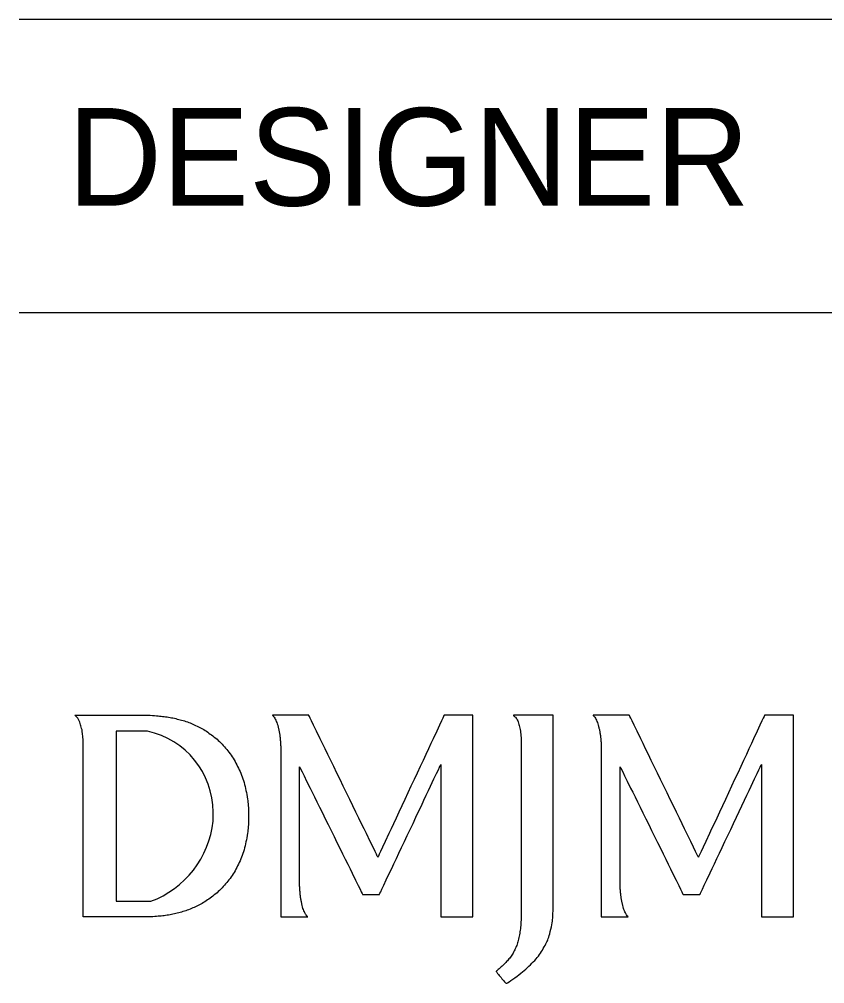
# Model space of a CAD drawing. Extents: x 0 to 3.5, y -0.08 to 2.5.
# Drawn here: x 3.1667 to 3.2526, y 1.7486 to 1.8514 of the extents above; entities that cross this region are included whole.
import ezdxf

# ---------------------------------------------------------------- set-up
doc = ezdxf.new("R2010")
doc.units = 0
doc.layers.add('G-ANNO-TTLB', color=7, linetype='Continuous')
doc.layers.add('G-DMJM-LOGO', color=7, linetype='Continuous')

msp = doc.modelspace()

# ---------------------------------------------------------------- linework, layer by layer
at = {"layer": 'G-ANNO-TTLB'}
msp.add_line((3.1666666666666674, 1.8201471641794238), (3.458333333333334, 1.8201471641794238), dxfattribs=at)
msp.add_lwpolyline([(3.1666666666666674, 1.8513971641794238), (3.458333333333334, 1.8513971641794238)], dxfattribs=at)
at = {"layer": 'G-DMJM-LOGO'}
for p, q in [((3.1803547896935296, 1.775481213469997), (3.1769871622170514, 1.775481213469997)), ((3.1803547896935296, 1.775481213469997), (3.1769871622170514, 1.775481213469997)), ((3.1873490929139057, 1.765896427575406), (3.1873490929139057, 1.7668462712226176)), ((3.1873490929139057, 1.765896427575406), (3.1873490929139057, 1.7668462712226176))]:
    msp.add_line(p, q, dxfattribs=at)
for points in [[(3.172585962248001, 1.7771885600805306), (3.1798756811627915, 1.7771885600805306)], [(3.172585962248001, 1.7771885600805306), (3.1798756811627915, 1.7771885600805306)], [(3.1769871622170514, 1.775481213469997), (3.1769871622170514, 1.7573478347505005), (3.1807001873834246, 1.7573478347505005)], [(3.1769871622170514, 1.775481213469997), (3.1769871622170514, 1.7573478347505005), (3.1807001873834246, 1.7573478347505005)], [(3.1799035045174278, 1.755681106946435), (3.173476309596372, 1.755681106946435), (3.173476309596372, 1.7740027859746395)], [(3.1799035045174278, 1.755681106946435), (3.173476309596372, 1.755681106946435), (3.173476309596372, 1.7740027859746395)]]:
    msp.add_lwpolyline(points, dxfattribs=at)
for centre, radius, start, end in [((3.1785010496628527, 1.7668295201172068), 0.008848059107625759, 0.1084721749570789, 77.90647292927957), ((3.1785010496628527, 1.7668295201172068), 0.008848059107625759, 0.1084721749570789, 77.90647292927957), ((3.177111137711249, 1.7669992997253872), 0.010297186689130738, 290.39844597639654, 353.8515867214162), ((3.177111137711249, 1.7669992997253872), 0.010297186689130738, 290.39844597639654, 353.8515867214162)]:
    msp.add_arc(centre, radius, start, end, dxfattribs=at)
for points in [[(3.173476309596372, 1.7740027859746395), (3.173476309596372, 1.7748374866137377), (3.1733997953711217, 1.7755191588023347), (3.17324676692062, 1.77604780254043), (3.173093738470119, 1.7765764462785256), (3.1728731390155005, 1.776956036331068), (3.172585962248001, 1.7771885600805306)], [(3.173476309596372, 1.7740027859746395), (3.173476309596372, 1.7748374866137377), (3.1733997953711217, 1.7755191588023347), (3.17324676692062, 1.77604780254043), (3.173093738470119, 1.7765764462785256), (3.1728731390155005, 1.776956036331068), (3.172585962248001, 1.7771885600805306)], [(3.1798756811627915, 1.7771885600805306), (3.180515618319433, 1.7771885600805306), (3.1811555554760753, 1.7771527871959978), (3.1817954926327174, 1.7770852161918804), (3.182435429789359, 1.7770136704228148), (3.183063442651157, 1.7769003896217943), (3.183680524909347, 1.776743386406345), (3.184297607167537, 1.7765843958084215), (3.1848977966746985, 1.7763697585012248), (3.1854820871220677, 1.7760954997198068), (3.186066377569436, 1.7758232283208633), (3.1866317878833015, 1.7754873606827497), (3.187179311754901, 1.7750878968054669), (3.187772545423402, 1.7746427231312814), (3.1883131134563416, 1.774124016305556), (3.1888000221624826, 1.7735297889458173), (3.189286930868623, 1.7729355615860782), (3.1897042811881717, 1.772275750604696), (3.19005207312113, 1.7715483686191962), (3.1903998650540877, 1.7708189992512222), (3.1906661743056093, 1.770026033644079), (3.190851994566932, 1.7691674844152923), (3.191036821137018, 1.7683109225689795), (3.191130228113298, 1.7673947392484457), (3.191130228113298, 1.7664209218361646)], [(3.1798756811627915, 1.7771885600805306), (3.180515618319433, 1.7771885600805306), (3.1811555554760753, 1.7771527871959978), (3.1817954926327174, 1.7770852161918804), (3.182435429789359, 1.7770136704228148), (3.183063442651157, 1.7769003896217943), (3.183680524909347, 1.776743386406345), (3.184297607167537, 1.7765843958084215), (3.1848977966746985, 1.7763697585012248), (3.1854820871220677, 1.7760954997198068), (3.186066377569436, 1.7758232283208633), (3.1866317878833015, 1.7754873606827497), (3.187179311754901, 1.7750878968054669), (3.187772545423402, 1.7746427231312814), (3.1883131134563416, 1.774124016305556), (3.1888000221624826, 1.7735297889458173), (3.189286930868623, 1.7729355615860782), (3.1897042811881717, 1.772275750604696), (3.19005207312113, 1.7715483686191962), (3.1903998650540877, 1.7708189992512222), (3.1906661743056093, 1.770026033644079), (3.190851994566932, 1.7691674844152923), (3.191036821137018, 1.7683109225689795), (3.191130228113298, 1.7673947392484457), (3.191130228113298, 1.7664209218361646)], [(3.2116439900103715, 1.755681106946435), (3.2116439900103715, 1.755681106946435), (3.2116439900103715, 1.7719438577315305), (3.2116439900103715, 1.7719438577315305), (3.2116439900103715, 1.7719438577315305), (3.2050915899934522, 1.758073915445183), (3.2050915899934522, 1.758073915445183), (3.2050915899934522, 1.758073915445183), (3.2032969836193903, 1.758073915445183), (3.2032969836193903, 1.758073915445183), (3.2032969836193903, 1.758073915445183), (3.1965776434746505, 1.7716934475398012), (3.1965776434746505, 1.7716934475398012), (3.1965776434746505, 1.7716934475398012), (3.1965776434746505, 1.7594094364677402), (3.1965776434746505, 1.7594094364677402), (3.1965776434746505, 1.7589642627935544), (3.1965985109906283, 1.7585429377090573), (3.196640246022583, 1.7581434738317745), (3.196681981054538, 1.7577440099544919), (3.1967396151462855, 1.7573823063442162), (3.1968141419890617, 1.7570583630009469), (3.1968876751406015, 1.756734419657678), (3.1969810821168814, 1.7564522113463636), (3.1970923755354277, 1.7562177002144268), (3.1972036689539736, 1.755979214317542), (3.1973239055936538, 1.7558003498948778), (3.1974540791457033, 1.755681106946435), (3.1974540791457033, 1.755681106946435), (3.1945604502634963, 1.755681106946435), (3.1945604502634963, 1.755681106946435), (3.1945604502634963, 1.755681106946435), (3.1945604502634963, 1.7734602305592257), (3.1945604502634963, 1.7734602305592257), (3.1945604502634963, 1.7739054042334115), (3.1945395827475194, 1.7743267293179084), (3.1944978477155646, 1.7747261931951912), (3.1944561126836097, 1.7751256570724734), (3.1943954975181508, 1.7754873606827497), (3.1943169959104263, 1.7758113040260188), (3.1942384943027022, 1.776135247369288), (3.1941450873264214, 1.7764174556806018), (3.1940387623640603, 1.7766519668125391), (3.1939324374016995, 1.7768904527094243), (3.1938092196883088, 1.7770673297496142), (3.1936701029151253, 1.7771885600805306), (3.1936701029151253, 1.7771885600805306), (3.1975514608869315, 1.7771885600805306), (3.1975514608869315, 1.7771885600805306), (3.1975514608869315, 1.7771885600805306), (3.204924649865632, 1.7620387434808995), (3.204924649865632, 1.7620387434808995), (3.204924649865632, 1.7620387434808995), (3.21199178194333, 1.7771885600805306), (3.21199178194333, 1.7771885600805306), (3.21199178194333, 1.7771885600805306), (3.2150662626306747, 1.7771885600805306), (3.2150662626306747, 1.7771885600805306), (3.2150662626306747, 1.7771885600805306), (3.2150662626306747, 1.755681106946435), (3.2150662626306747, 1.755681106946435), (3.2150662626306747, 1.755681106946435), (3.2116439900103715, 1.755681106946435), (3.2116439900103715, 1.755681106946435)], [(3.223380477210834, 1.7543654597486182), (3.223222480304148, 1.7536480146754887), (3.222954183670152, 1.752964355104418), (3.2225735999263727, 1.7523144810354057), (3.222193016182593, 1.7516665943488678), (3.2216802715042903, 1.751036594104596), (3.2210363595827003, 1.7504304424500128), (3.2203914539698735, 1.7498223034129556), (3.2195825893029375, 1.7491982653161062), (3.2186087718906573, 1.7485583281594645), (3.2186087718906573, 1.7485583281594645), (3.2175236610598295, 1.7498660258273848), (3.2175236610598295, 1.7498660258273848), (3.217996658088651, 1.7502555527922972), (3.218402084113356, 1.7506371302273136), (3.2187409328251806, 1.7510147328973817), (3.219078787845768, 1.7513883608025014), (3.2193570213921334, 1.7518136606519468), (3.219575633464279, 1.7522866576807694), (3.2197932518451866, 1.7527596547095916), (3.219953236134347, 1.7533081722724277), (3.22005558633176, 1.7539361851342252), (3.2201579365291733, 1.7545602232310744), (3.220208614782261, 1.7553233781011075), (3.220208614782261, 1.7562236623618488), (3.220208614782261, 1.7562236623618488), (3.220208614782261, 1.7740027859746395), (3.220208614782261, 1.7740027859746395), (3.220208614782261, 1.7748374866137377), (3.2201390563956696, 1.7755271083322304), (3.219999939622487, 1.7760756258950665), (3.2198608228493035, 1.776622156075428), (3.219633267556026, 1.7769937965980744), (3.2193182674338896, 1.7771885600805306), (3.2193182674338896, 1.7771885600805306), (3.2236169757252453, 1.7771885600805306), (3.2236169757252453, 1.7771885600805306), (3.2236169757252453, 1.7771885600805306), (3.2236169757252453, 1.756738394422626), (3.2236169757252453, 1.756738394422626), (3.2236169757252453, 1.7558758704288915), (3.223538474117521, 1.7550848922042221), (3.223380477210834, 1.7543654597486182)], [(3.245841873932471, 1.755681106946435), (3.245841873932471, 1.755681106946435), (3.245841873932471, 1.7719438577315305), (3.245841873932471, 1.7719438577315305), (3.245841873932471, 1.7719438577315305), (3.2392894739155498, 1.758073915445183), (3.2392894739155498, 1.758073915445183), (3.2392894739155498, 1.758073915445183), (3.237494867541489, 1.758073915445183), (3.237494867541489, 1.758073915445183), (3.237494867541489, 1.758073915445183), (3.2307755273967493, 1.7716934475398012), (3.2307755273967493, 1.7716934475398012), (3.2307755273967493, 1.7716934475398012), (3.2307755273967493, 1.7594094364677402), (3.2307755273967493, 1.7594094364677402), (3.2307755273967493, 1.7589642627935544), (3.2307963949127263, 1.7585429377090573), (3.2308381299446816, 1.7581434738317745), (3.2308798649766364, 1.7577440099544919), (3.2309374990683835, 1.7573823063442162), (3.2310120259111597, 1.7570583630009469), (3.231086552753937, 1.756734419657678), (3.23117896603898, 1.7564522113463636), (3.2312902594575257, 1.7562177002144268), (3.2314015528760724, 1.755979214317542), (3.231521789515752, 1.7558003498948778), (3.2316519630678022, 1.755681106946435), (3.2316519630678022, 1.755681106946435), (3.228758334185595, 1.755681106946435), (3.228758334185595, 1.755681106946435), (3.228758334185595, 1.755681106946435), (3.228758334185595, 1.7734602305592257), (3.228758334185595, 1.7734602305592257), (3.228758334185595, 1.7739054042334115), (3.228737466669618, 1.7743267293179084), (3.228695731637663, 1.7747261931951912), (3.228653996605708, 1.7751256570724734), (3.22859338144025, 1.7754873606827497), (3.228514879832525, 1.7758113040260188), (3.228435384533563, 1.776135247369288), (3.2283429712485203, 1.7764174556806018), (3.2282366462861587, 1.7766519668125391), (3.22812932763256, 1.7768904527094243), (3.228007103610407, 1.7770673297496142), (3.227867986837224, 1.7771885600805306), (3.227867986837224, 1.7771885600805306), (3.23174934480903, 1.7771885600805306), (3.23174934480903, 1.7771885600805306), (3.23174934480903, 1.7771885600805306), (3.239122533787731, 1.7620387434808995), (3.239122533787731, 1.7620387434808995), (3.239122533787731, 1.7620387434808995), (3.2461896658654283, 1.7771885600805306), (3.2461896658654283, 1.7771885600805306), (3.2461896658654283, 1.7771885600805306), (3.2492641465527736, 1.7771885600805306), (3.2492641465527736, 1.7771885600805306), (3.2492641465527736, 1.7771885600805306), (3.2492641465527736, 1.755681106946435), (3.2492641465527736, 1.755681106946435), (3.2492641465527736, 1.755681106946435), (3.245841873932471, 1.755681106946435), (3.245841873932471, 1.755681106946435)], [(3.191130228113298, 1.7664209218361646), (3.191130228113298, 1.7654471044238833), (3.191036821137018, 1.7645329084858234), (3.190851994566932, 1.763680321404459), (3.1906661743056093, 1.7628277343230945), (3.1903998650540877, 1.7620387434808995), (3.19005207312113, 1.7613153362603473), (3.1897042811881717, 1.7605919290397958), (3.189286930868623, 1.7599360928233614), (3.1888000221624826, 1.7593458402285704), (3.1883131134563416, 1.7587575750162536), (3.187772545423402, 1.7582408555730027), (3.187179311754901, 1.757795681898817), (3.186622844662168, 1.757378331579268), (3.1860524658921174, 1.757034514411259), (3.1854681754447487, 1.7567662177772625), (3.1848838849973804, 1.7564959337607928), (3.1842856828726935, 1.7562812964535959), (3.1836735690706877, 1.7561183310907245), (3.1830614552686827, 1.755957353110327), (3.1824394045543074, 1.7558440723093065), (3.181809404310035, 1.7557784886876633), (3.1811784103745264, 1.75571290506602), (3.1805434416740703, 1.755681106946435), (3.1799035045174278, 1.755681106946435)], [(3.191130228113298, 1.7664209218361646), (3.191130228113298, 1.7654471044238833), (3.191036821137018, 1.7645329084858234), (3.190851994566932, 1.763680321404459), (3.1906661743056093, 1.7628277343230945), (3.1903998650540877, 1.7620387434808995), (3.19005207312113, 1.7613153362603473), (3.1897042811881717, 1.7605919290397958), (3.189286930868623, 1.7599360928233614), (3.1888000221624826, 1.7593458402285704), (3.1883131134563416, 1.7587575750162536), (3.187772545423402, 1.7582408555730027), (3.187179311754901, 1.757795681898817), (3.186622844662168, 1.757378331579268), (3.1860524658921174, 1.757034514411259), (3.1854681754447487, 1.7567662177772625), (3.1848838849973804, 1.7564959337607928), (3.1842856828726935, 1.7562812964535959), (3.1836735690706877, 1.7561183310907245), (3.1830614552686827, 1.755957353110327), (3.1824394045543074, 1.7558440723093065), (3.181809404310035, 1.7557784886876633), (3.1811784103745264, 1.75571290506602), (3.1805434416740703, 1.755681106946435), (3.1799035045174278, 1.755681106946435)]]:
    msp.add_open_spline(points, degree=3, dxfattribs=at)

# ---------------------------------------------------------------- texts
at = {"layer": 'G-ANNO-TTLB'}
msp.add_text('DESIGNER', height=0.010416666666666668, dxfattribs=at).set_placement((3.1718334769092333, 1.831520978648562))

doc.saveas('drawing.dxf')
